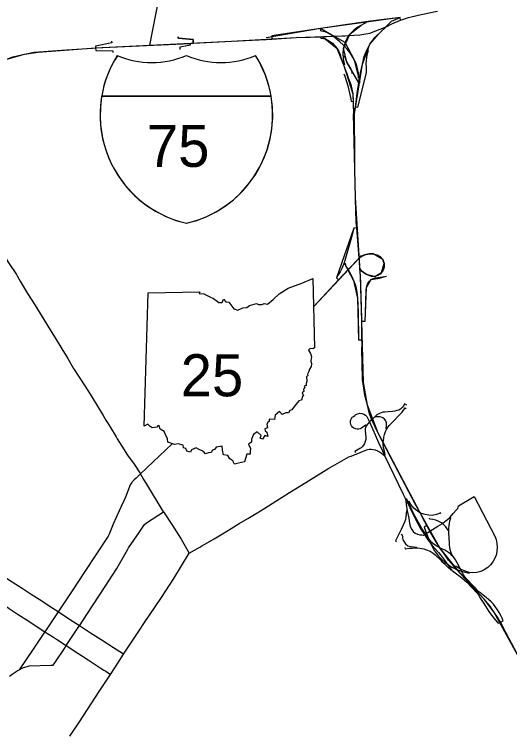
# Model space of a CAD drawing. Extents: x 0 to 750, y 0 to 507.
# Drawn here: x 349.21 to 379.68, y 258.49 to 302.57 of the extents above; entities that cross this region are included whole.
import ezdxf

# ---------------------------------------------------------------- set-up
doc = ezdxf.new("R2010")
doc.units = 0
for name, color, linetype in [('GM_P_US_Alignment', 7, 'Continuous'), ('GM_X_Interchange_Ramps', 7, 'Continuous'), ('GM_X_Interstate_Route', 7, 'Continuous'), ('GM_X_State_Route', 7, 'Continuous'), ('SH_Data', 7, 'Continuous')]:
    doc.layers.add(name, color=color, linetype=linetype)

msp = doc.modelspace()

# ---------------------------------------------------------------- linework, layer by layer
at = {"layer": 'GM_P_US_Alignment'}
for points in [[(370.147, 296.454), (370.629, 299.509), (371.075, 300.734), (371.605, 301.353), (372.411, 302.16), (372.954, 302.377), (368.055, 301.698), (364.701, 301.126)], [(370.496, 298.378), (370.147, 299.745), (369.564, 300.837), (368.055, 301.698)], [(370.396, 298.362), (369.661, 299.63), (369.459, 300.495), (369.879, 301.375), (370.529, 301.893)], [(343.47, 298.742), (344.535, 298.603), (345.804, 298.696), (346.876, 299.049), (348.761, 299.812), (349.837, 300.119), (350.674, 300.247), (354.214, 300.508), (362.568, 300.914), (366.547, 301.142), (368.825, 301.223)], [(368.153, 301.202), (369.043, 300.485), (369.5, 299.366), (370.043, 297.689), (370.08, 296.454)], [(380.488, 262.562), (378.714, 265.798), (378.115, 266.581), (376.609, 268.21), (375.388, 269.749), (373.902, 272.374), (372.62, 274.824), (371.601, 276.797), (370.929, 278.518), (370.691, 279.91), (370.58, 283.693), (370.508, 286.44), (370.197, 291.277), (370.08, 296.454)], [(370.272, 289.427), (370.089, 289.418), (369.03, 286.363), (369.156, 286.237)], [(370.569, 286.788), (370.846, 286.582), (371.387, 286.445), (371.808, 286.684), (371.96, 287.235), (371.878, 287.478), (371.296, 287.838), (371.045, 287.829), (370.78, 287.761), (370.427, 287.575), (367.64, 284.59)], [(369.495, 287.27), (370.081, 286.185), (370.328, 285.104), (370.371, 284.24), (370.389, 282.532)], [(370.784, 283.685), (370.875, 285.764), (371.172, 286.245), (371.667, 286.344), (372.108, 286.462)]]:
    msp.add_lwpolyline(points, dxfattribs=at)
at = {"layer": 'GM_X_Interchange_Ramps'}
for points in [[(372.959, 302.218), (372.954, 302.377), (371.122, 302.15), (370.834, 302.109), (369.43, 301.908), (368.055, 301.698), (365.055, 301.239), (365.062, 301.051)], [(370.834, 302.109), (370.836, 302.04), (370.714, 301.981), (370.529, 301.893), (370.341, 301.774), (370.096, 301.592), (369.879, 301.375), (369.772, 301.268), (369.648, 301.033), (369.564, 300.837), (369.494, 300.634), (369.459, 300.495), (369.435, 300.365), (369.428, 300.224), (369.428, 300.059), (369.433, 299.99), (369.446, 299.793), (369.514, 299.489), (369.459, 299.467)], [(370.441, 298.661), (370.38, 298.668), (370.375, 298.954), (370.345, 299.137), (370.311, 299.319), (370.239, 299.52), (370.147, 299.745), (370.002, 299.999), (369.872, 300.192), (369.686, 300.423), (369.494, 300.634), (369.459, 300.673), (369.212, 300.907), (368.998, 301.093), (368.825, 301.223), (368.784, 301.254), (368.522, 301.414), (368.331, 301.49), (368.126, 301.541), (368.06, 301.552), (368.055, 301.698)], [(360.218, 300.793), (360.208, 301.029), (359.304, 301.104), (359.3, 301.104), (359.297, 301.179)], [(359.297, 301.179), (359.304, 301.104), (360.208, 301.029), (360.218, 300.793)], [(368.074, 301.196), (368.077, 301.11), (368.093, 301.108), (368.35, 301.058), (368.604, 300.924), (368.786, 300.791), (368.93, 300.639), (369.043, 300.485), (369.17, 300.286), (369.249, 300.094), (369.318, 299.863), (369.397, 299.62), (369.459, 299.467), (369.5, 299.366), (369.548, 299.211), (369.656, 298.92), (369.754, 298.656), (369.922, 298.251), (370.043, 297.689), (370.064, 297.227), (370.08, 296.454), (370.147, 296.454)], [(355.199, 300.926), (355.207, 300.813), (354.208, 300.604), (354.214, 300.508)], [(359.421, 300.411), (359.408, 300.566), (359.837, 300.66), (360.052, 300.695), (360.048, 300.785)], [(359.421, 300.411), (359.408, 300.566), (359.837, 300.66), (360.052, 300.695), (360.048, 300.785)], [(354.214, 300.508), (354.218, 300.35), (355.272, 300.318), (355.264, 300.231)], [(370.874, 298.989), (370.876, 299.085), (370.868, 299.293), (370.857, 299.534), (370.872, 299.723), (370.894, 299.896), (370.926, 300.071), (370.965, 300.227), (371.006, 300.364), (370.912, 300.405)], [(369.433, 299.99), (369.514, 300.004), (369.582, 299.802), (369.661, 299.63), (369.764, 299.438), (369.905, 299.194), (369.976, 299.023), (369.984, 298.937)], [(369.491, 298.913), (369.535, 298.761), (369.718, 298.18), (369.914, 297.372), (369.941, 297.217), (370.064, 297.227)], [(370.193, 296.874), (370.337, 296.858), (370.865, 298.885), (370.874, 298.989)], [(370.272, 289.427), (370.089, 289.418), (370.024, 289.08), (369.894, 288.633), (369.495, 287.27), (369.356, 286.922), (369.247, 286.718), (369.135, 286.541), (369.03, 286.363), (369.156, 286.237)], [(369.495, 287.27), (369.56, 287.235), (369.603, 287.061), (369.66, 286.966), (369.738, 286.875)], [(369.738, 286.875), (369.816, 286.753), (369.946, 286.484), (370.081, 286.185), (370.172, 285.942), (370.233, 285.716), (370.28, 285.473), (370.328, 285.104), (370.361, 283.488), (370.364, 283.341), (370.389, 282.532), (370.598, 282.532)], [(370.58, 283.693), (370.784, 283.685), (370.819, 284.175), (370.862, 285.59), (370.875, 285.764), (370.908, 285.906), (370.961, 286.022), (371.056, 286.152), (371.172, 286.245), (371.287, 286.305), (371.422, 286.358), (372.008, 286.445), (372.108, 286.462)], [(373.363, 278.529), (373.221, 278.6), (373.164, 278.498), (373.071, 278.381), (372.958, 278.281), (372.861, 278.222), (372.742, 278.184), (372.628, 278.151), (372.466, 278.129), (372.2, 278.114), (372.003, 278.097), (371.882, 278.079), (371.787, 278.05), (371.675, 277.999), (371.517, 277.915), (371.391, 277.81), (371.276, 277.704), (371.196, 277.623), (371.131, 277.565), (371.054, 277.485), (370.951, 277.376), (370.873, 277.265), (370.823, 277.157), (370.801, 277.055), (370.799, 276.942), (370.836, 276.551), (370.827, 276.415), (370.803, 276.291), (370.758, 276.163), (370.697, 276.052), (370.616, 275.961), (370.539, 275.903), (370.463, 275.855), (370.161, 275.675), (370.197, 275.598)], [(371.983, 275.432), (372.029, 275.458), (371.974, 275.697), (371.947, 275.812), (371.919, 275.951), (371.911, 276.048), (371.905, 276.216), (371.917, 276.351), (371.934, 276.491), (371.944, 276.555), (371.985, 276.717), (372.019, 276.831), (372.062, 276.936), (372.106, 277.029), (372.169, 277.134), (372.27, 277.27), (372.408, 277.418), (372.989, 278.001), (373.073, 278.087), (373.262, 278.347), (373.314, 278.324)], [(370.873, 277.265), (370.812, 277.298), (370.559, 277.106), (370.488, 277.067), (370.396, 277.037), (370.296, 277.04), (370.194, 277.061), (370.102, 277.1), (370.02, 277.157), (369.948, 277.244), (369.907, 277.328), (369.89, 277.443), (369.894, 277.547), (369.916, 277.621), (369.952, 277.708), (370.003, 277.775), (370.067, 277.83), (370.15, 277.894), (370.23, 277.94), (370.336, 277.991), (370.444, 278.018), (370.598, 278.014), (370.713, 277.968), (370.814, 277.901), (370.892, 277.816), (370.941, 277.736), (371.054, 277.485), (371.623, 276.222), (371.855, 275.713), (371.958, 275.484), (371.983, 275.432)], [(372.106, 277.029), (372.076, 277.072), (372.101, 277.29), (372.101, 277.424), (372.061, 277.552), (371.981, 277.664), (371.875, 277.741), (371.773, 277.777), (371.693, 277.799), (371.602, 277.806), (371.493, 277.799), (371.413, 277.781), (371.391, 277.81)], [(376.169, 269.269), (376.151, 269.253), (376.064, 269.342), (375.93, 269.447), (375.807, 269.531), (375.695, 269.588), (375.518, 269.676), (375.388, 269.749), (375.356, 269.765), (375.195, 269.845), (375.04, 269.945), (374.901, 270.066), (374.762, 270.216), (374.674, 270.347), (374.506, 270.595), (374.277, 270.926), (373.977, 271.482), (373.77, 271.859), (373.433, 272.565), (373.333, 272.765), (373.267, 272.727)], [(373.3, 272.584), (373.367, 272.608), (373.717, 271.834), (373.917, 271.459), (374.216, 270.894), (374.439, 270.553), (374.651, 270.227), (374.803, 270.032), (374.915, 269.89), (375.302, 269.458), (375.418, 269.312), (375.62, 269.066), (375.807, 268.802), (375.84, 268.747), (376.003, 268.511), (376.111, 268.388), (376.135, 268.361), (376.253, 268.256), (376.417, 268.138), (376.645, 267.969), (376.89, 267.764), (377.038, 267.628), (377.69, 266.95), (377.78, 266.819), (377.87, 266.65), (378.047, 266.38), (378.188, 266.148), (378.402, 265.825), (378.62, 265.52), (378.916, 265.156), (378.98, 265.097), (379.114, 265.163)], [(375.451, 271.834), (375.423, 271.888), (375.303, 271.836), (375.181, 271.793), (374.916, 271.736), (374.709, 271.752), (374.478, 271.784), (374.258, 271.852), (374.171, 271.901), (374.007, 271.991), (373.789, 272.183), (373.613, 272.399), (373.494, 272.596), (373.433, 272.565)], [(373.379, 272.012), (373.33, 272.009), (373.321, 271.832), (373.3, 271.657), (373.266, 271.486), (373.222, 271.33), (373.13, 271.134), (373.002, 270.877), (372.786, 270.417), (372.662, 270.164), (372.714, 270.124)], [(375.937, 270.792), (375.891, 270.787), (375.843, 270.917), (375.762, 271.042), (375.682, 271.122), (375.546, 271.242), (375.489, 271.275), (375.291, 271.385), (375.144, 271.438), (374.949, 271.482), (374.767, 271.495), (374.761, 271.557)], [(379.114, 265.163), (379.292, 265.245), (379.224, 265.413), (379.142, 265.584), (379.035, 265.77), (378.941, 265.922), (378.8, 266.123), (378.682, 266.267), (378.541, 266.417), (378.381, 266.56), (378.227, 266.685), (378.051, 266.827), (377.901, 266.949), (377.79, 267.041), (377.487, 267.351), (376.991, 267.878), (376.877, 268.027), (376.779, 268.19), (376.723, 268.299), (376.652, 268.433), (376.433, 268.855), (376.349, 269.003), (376.26, 269.123), (376.169, 269.269), (376.091, 269.442), (376.032, 269.631), (376.005, 269.754), (375.982, 269.922), (375.955, 270.43), (375.941, 270.587), (375.937, 270.792), (375.932, 270.897), (375.953, 271.131), (375.975, 271.247), (376.007, 271.411), (376.064, 271.579), (376.025, 271.627)], [(374.591, 271.107), (374.414, 271.01), (374.562, 270.631), (374.674, 270.347), (374.803, 270.032), (374.97, 269.705), (375.064, 269.552), (375.178, 269.388), (375.309, 269.225), (375.509, 269.021), (375.724, 268.835), (375.84, 268.747), (376.124, 268.558), (376.393, 268.424), (376.413, 268.415), (376.723, 268.299), (376.953, 268.239), (377.186, 268.179), (377.188, 268.23)], [(373.006, 270.582), (373.08, 270.546), (373.087, 270.394), (373.121, 270.234), (373.191, 270.1), (373.282, 269.985), (373.414, 269.873), (373.613, 269.825), (373.951, 269.776), (373.954, 269.743)], [(373.23, 269.754), (373.255, 269.683), (373.512, 269.716), (373.694, 269.725), (373.837, 269.739), (373.954, 269.743), (374.15, 269.722), (374.4, 269.681), (374.57, 269.627), (374.788, 269.534), (374.984, 269.408), (375.102, 269.316), (375.418, 268.999), (375.515, 268.904), (375.625, 268.798), (375.887, 268.55), (376.089, 268.363), (376.111, 268.388)]]:
    msp.add_lwpolyline(points, dxfattribs=at)
at = {"layer": 'GM_X_Interstate_Route'}
for p, q in [((354.585, 297.533), (365.009, 297.533)), ((365.009, 297.533), (354.585, 297.533)), ((365.009, 297.533), (354.585, 297.533)), ((357.208, 277.235), (357.438, 285.442)), ((357.208, 277.235), (357.438, 285.442))]:
    msp.add_line(p, q, dxfattribs=at)
for points in [[(372.088, 301.799), (372.436, 301.978), (372.959, 302.218), (373.469, 302.386), (374.053, 302.513), (375.127, 302.741), (375.239, 302.766)], [(369.526, 301.252), (369.536, 301.253), (369.772, 301.268), (370.473, 301.313), (371.073, 301.418), (372.088, 301.799)], [(370.912, 300.405), (371.075, 300.734), (371.386, 301.138), (372.088, 301.799)], [(348.321, 299.62), (348.483, 299.69), (348.761, 299.812), (349.118, 299.953), (349.47, 300.048), (349.837, 300.119), (350.425, 300.236), (352.431, 300.391), (354.021, 300.496), (354.214, 300.508), (357.336, 300.661), (360.048, 300.785), (360.218, 300.793), (362.568, 300.914), (364.7, 301.031), (365.062, 301.051), (366.547, 301.142), (367.419, 301.173)], [(367.419, 301.173), (368.074, 301.196), (368.825, 301.223), (369.391, 301.244), (369.526, 301.252)], [(370.42, 298.524), (370.441, 298.661), (370.517, 298.965), (370.629, 299.509), (370.742, 299.977), (370.819, 300.183), (370.912, 300.405)], [(370.272, 289.427), (370.242, 289.763), (370.235, 289.864), (370.221, 290.428), (370.197, 291.277), (370.16, 293.027), (370.15, 294.512), (370.134, 295.707), (370.147, 296.454), (370.193, 296.874), (370.321, 297.87), (370.396, 298.362), (370.42, 298.524)], [(370.444, 287.34), (370.427, 287.575), (370.272, 289.427)], [(370.472, 286.948), (370.444, 287.34)], [(370.532, 286), (370.508, 286.44), (370.472, 286.948)], [(357.438, 285.442), (360.623, 285.496), (360.573, 285.397), (360.873, 285.376), (361.192, 285.2), (361.462, 285.09), (361.793, 284.829), (361.99, 284.832), (362.074, 285.046), (362.225, 284.881), (362.405, 284.851), (362.715, 284.458), (362.971, 284.373), (363.278, 284.508), (363.508, 284.53), (363.675, 284.663), (364.112, 284.777), (364.234, 284.709), (364.465, 284.722), (364.582, 284.773), (364.784, 284.728), (365.139, 285.026), (365.504, 285.378), (366.067, 285.71), (366.907, 286.025), (367.571, 286.306), (367.667, 282.047)], [(357.438, 285.442), (360.623, 285.496), (360.573, 285.397), (360.873, 285.376), (361.192, 285.2), (361.462, 285.09), (361.793, 284.829), (361.99, 284.832), (362.074, 285.046), (362.225, 284.881), (362.405, 284.851), (362.715, 284.458), (362.971, 284.373), (363.278, 284.508), (363.508, 284.53), (363.675, 284.663), (364.112, 284.777), (364.234, 284.709), (364.465, 284.722), (364.582, 284.773), (364.784, 284.728), (365.139, 285.026), (365.504, 285.378), (366.067, 285.71), (366.907, 286.025), (367.571, 286.306), (367.667, 282.047)], [(374.724, 270.857), (374.591, 271.107), (374.348, 271.566), (374.171, 271.901), (373.554, 273.069), (371.905, 276.216), (371.819, 276.381), (371.601, 276.797), (371.196, 277.623), (371.061, 277.995), (370.929, 278.518), (370.77, 279.145), (370.706, 279.564), (370.638, 280.107), (370.615, 281.12), (370.61, 281.202), (370.598, 281.85), (370.607, 282.35), (370.598, 282.532), (370.593, 283.116), (370.58, 283.693), (370.579, 283.846), (370.559, 284.554), (370.541, 285.22), (370.537, 285.911), (370.532, 286)], [(367.667, 282.047), (367.569, 281.987), (367.416, 282.015), (367.314, 281.896), (367.441, 281.696), (367.501, 281.486), (367.448, 281.254), (367.5, 281.062), (367.464, 280.902), (367.368, 280.743), (367.335, 280.591), (367.254, 280.43), (367.261, 280.341), (367.183, 280.27), (367.197, 280.003), (367.158, 279.856), (367.171, 279.729), (367.045, 279.695), (367.074, 279.59), (366.994, 279.509), (367.011, 279.369), (366.92, 279.28), (367.008, 279.101), (366.937, 279.044), (366.879, 278.827), (366.717, 278.783), (366.393, 278.385), (366.279, 278.235), (366.15, 278.198), (366.08, 278.043), (365.922, 278.043), (365.682, 277.936), (365.528, 278.12), (365.257, 277.898), (365.225, 277.642), (364.883, 277.651), (364.896, 277.521), (364.82, 277.484), (364.75, 277.354), (364.791, 277.124), (364.63, 277.065), (364.65, 276.931), (364.752, 276.849), (364.798, 276.594), (364.628, 276.646), (364.488, 276.43), (364.344, 276.481), (364.391, 276.663), (364.149, 276.883), (363.919, 276.707), (363.8, 276.426), (363.798, 276.237), (363.627, 276.123), (363.737, 275.856), (363.717, 275.672), (363.72, 275.498), (363.506, 275.504), (363.377, 275.033)], [(367.667, 282.047), (367.569, 281.987), (367.416, 282.015), (367.314, 281.896), (367.441, 281.696), (367.501, 281.486), (367.448, 281.254), (367.5, 281.062), (367.464, 280.902), (367.368, 280.743), (367.335, 280.591), (367.254, 280.43), (367.261, 280.341), (367.183, 280.27), (367.197, 280.003), (367.158, 279.856), (367.171, 279.729), (367.045, 279.695), (367.074, 279.59), (366.994, 279.509), (367.011, 279.369), (366.92, 279.28), (367.008, 279.101), (366.937, 279.044), (366.879, 278.827), (366.717, 278.783), (366.393, 278.385), (366.279, 278.235), (366.15, 278.198), (366.08, 278.043), (365.922, 278.043), (365.682, 277.936), (365.528, 278.12), (365.257, 277.898), (365.225, 277.642), (364.883, 277.651), (364.896, 277.521), (364.82, 277.484), (364.75, 277.354), (364.791, 277.124), (364.63, 277.065), (364.65, 276.931), (364.752, 276.849), (364.798, 276.594), (364.628, 276.646), (364.488, 276.43), (364.344, 276.481), (364.391, 276.663), (364.149, 276.883), (363.919, 276.707), (363.8, 276.426), (363.798, 276.237), (363.627, 276.123), (363.737, 275.856), (363.717, 275.672), (363.72, 275.498), (363.506, 275.504), (363.377, 275.033)], [(363.377, 275.033), (363.005, 274.943), (362.747, 274.889), (362.656, 275.103), (362.472, 275.215), (362.352, 275.431), (362.087, 275.46), (362.024, 275.756), (361.995, 275.996), (361.633, 275.937), (361.533, 275.79), (361.405, 275.751), (361.33, 275.603), (361.155, 275.591), (360.967, 275.521), (360.844, 275.666), (360.536, 275.812), (360.398, 275.887), (360.108, 275.77), (360.047, 275.632), (359.816, 275.693), (359.762, 275.847), (359.623, 275.893), (359.592, 276.057), (359.294, 276.144), (359.066, 276.109), (358.664, 276.241), (358.64, 276.456), (358.503, 276.718), (358.432, 276.9), (358.177, 277.039), (358.126, 277.255), (358.045, 277.249), (357.97, 277.161), (357.688, 277.121), (357.575, 277.209), (357.417, 277.36), (357.208, 277.235)], [(363.377, 275.033), (363.005, 274.943), (362.747, 274.889), (362.656, 275.103), (362.472, 275.215), (362.352, 275.431), (362.087, 275.46), (362.024, 275.756), (361.995, 275.996), (361.633, 275.937), (361.533, 275.79), (361.405, 275.751), (361.33, 275.603), (361.155, 275.591), (360.967, 275.521), (360.844, 275.666), (360.536, 275.812), (360.398, 275.887), (360.108, 275.77), (360.047, 275.632), (359.816, 275.693), (359.762, 275.847), (359.623, 275.893), (359.592, 276.057), (359.294, 276.144), (359.066, 276.109), (358.664, 276.241), (358.64, 276.456), (358.503, 276.718), (358.432, 276.9), (358.177, 277.039), (358.126, 277.255), (358.045, 277.249), (357.97, 277.161), (357.688, 277.121), (357.575, 277.209), (357.417, 277.36), (357.208, 277.235)], [(376.225, 268.627), (375.93, 268.99), (375.664, 269.343), (375.388, 269.749), (375.096, 270.206), (374.775, 270.759), (374.724, 270.857)], [(378.541, 266.047), (378.456, 266.17), (378.115, 266.581), (377.773, 266.958), (376.413, 268.415), (376.283, 268.555), (376.225, 268.627)], [(379.292, 264.838), (379.279, 264.862), (379.114, 265.163), (378.944, 265.47), (378.714, 265.798), (378.541, 266.047)], [(382.857, 257.191), (382.546, 257.645), (382.309, 258.124), (382.037, 258.845), (381.875, 259.365), (381.727, 259.787), (381.611, 260.139), (381.491, 260.445), (381.31, 260.871), (381.114, 261.332), (381.088, 261.394), (380.661, 262.212), (380.488, 262.562), (379.292, 264.838)]]:
    msp.add_lwpolyline(points, dxfattribs=at)
for centre, radius, start, end in [((361.339, 296.385), 6.851, 147.8216, 256.9941), ((360.911, 296.504), 6.409, 146.654, 170.759), ((357.669, 305.069), 5.467, 247.0848, 292.9105), ((357.669, 305.069), 5.467, 247.0848, 292.9105), ((358.255, 296.385), 6.851, 283.0065, 32.1787), ((361.925, 305.07), 5.468, 247.0916, 292.9084), ((361.925, 305.07), 5.468, 247.0916, 292.9084), ((358.255, 296.385), 6.851, 9.6475, 32.179), ((361.339, 296.385), 6.851, 170.3514, 256.9967), ((358.269, 296.382), 6.838, 282.7667, 9.6898)]:
    msp.add_arc(centre, radius, start, end, dxfattribs=at)
at = {"layer": 'GM_X_State_Route'}
for points in [[(346.637, 290.936), (347.566, 289.411), (347.989, 288.765), (348.221, 288.351), (348.403, 288.042), (348.838, 287.316), (349.336, 286.555), (349.383, 286.471), (349.564, 286.141), (350.015, 285.386), (350.468, 284.692), (350.639, 284.42), (351.424, 283.165), (351.784, 282.568), (352.133, 281.988), (352.511, 281.391), (352.86, 280.786), (353.205, 280.235), (353.588, 279.638), (353.974, 279.041), (354.319, 278.461), (354.668, 277.885), (354.832, 277.599), (354.914, 277.472)], [(368.635, 285.671), (369.156, 286.237), (369.738, 286.875), (370.427, 287.575), (370.556, 287.706)], [(368.635, 285.671), (369.156, 286.237), (369.738, 286.875), (370.427, 287.575), (370.556, 287.706)], [(368.635, 285.671), (369.156, 286.237), (369.738, 286.875), (370.427, 287.575), (370.556, 287.706)], [(370.556, 287.706), (370.78, 287.761), (371.045, 287.829), (371.296, 287.838), (371.53, 287.777), (371.717, 287.669), (371.878, 287.478), (371.96, 287.235), (371.96, 287.014), (371.895, 286.827), (371.808, 286.684), (371.708, 286.584), (371.578, 286.501), (371.387, 286.445), (371.179, 286.441), (371.023, 286.497), (370.846, 286.582), (370.691, 286.678), (370.569, 286.788), (370.472, 286.948)], [(367.64, 284.59), (368.635, 285.671)], [(367.64, 284.59), (368.635, 285.671)], [(367.64, 284.59), (368.635, 285.671)], [(354.914, 277.472), (355.131, 277.136), (355.475, 276.577), (355.534, 276.455), (355.828, 276.005), (356.182, 275.434), (356.586, 274.894), (356.964, 274.297)], [(356.964, 274.297), (358.914, 276.15)], [(369.783, 275.348), (369.926, 275.382), (370.478, 275.602), (370.882, 275.766), (371.036, 275.807), (371.166, 275.81), (371.29, 275.801), (371.417, 275.769), (371.559, 275.714), (371.669, 275.651), (371.793, 275.561), (371.891, 275.491), (371.983, 275.432)], [(368.555, 274.634), (368.779, 274.772), (369.783, 275.348)], [(371.983, 275.432), (373.123, 273.043), (373.224, 272.834)], [(356.964, 274.297), (356.7, 274.037)], [(358.395, 271.965), (357.37, 273.652), (357.144, 274.014), (356.964, 274.297)], [(363.985, 271.798), (364.088, 271.861), (364.626, 272.181), (365.074, 272.466), (366.133, 273.154), (367.139, 273.765), (368.555, 274.634)], [(356.449, 273.765), (356.344, 273.608), (356.047, 272.864), (355.66, 272.023), (355.3, 271.187), (355.041, 270.586)], [(356.7, 274.037), (356.578, 273.916), (356.469, 273.795), (356.449, 273.765)], [(377.501, 272.898), (378.763, 270.464), (378.846, 270.243), (378.896, 270.017), (378.915, 269.782), (378.892, 269.52), (378.846, 269.28), (378.758, 269.059), (378.657, 268.87), (378.51, 268.686), (378.335, 268.529), (378.118, 268.382), (377.902, 268.29), (377.671, 268.23), (377.418, 268.198), (377.188, 268.23), (376.957, 268.299), (376.741, 268.383), (376.652, 268.433), (376.553, 268.491), (376.384, 268.585), (376.225, 268.627)], [(376.545, 272.327), (377.501, 272.898)], [(373.224, 272.834), (373.233, 272.813), (373.267, 272.727), (373.293, 272.631), (373.3, 272.584), (373.323, 272.424), (373.379, 272.012), (373.475, 271.567), (373.505, 271.383), (373.531, 271.265), (373.549, 271.155), (373.585, 271.002), (373.659, 270.863), (373.738, 270.75), (373.864, 270.65), (374.003, 270.581), (374.151, 270.546), (374.277, 270.533), (374.392, 270.524)], [(374.392, 270.524), (374.439, 270.553), (374.483, 270.58), (374.506, 270.595), (374.562, 270.631), (374.611, 270.662), (374.775, 270.759), (375.269, 271.065), (375.407, 271.146), (375.546, 271.242), (375.702, 271.353), (375.863, 271.477), (376.025, 271.627), (376.21, 271.852), (376.405, 272.073), (376.491, 272.169), (376.545, 272.327)], [(356.171, 269.609), (356.242, 269.737), (356.887, 270.692), (357.211, 271.181), (357.338, 271.271), (358.395, 271.965)], [(358.395, 271.965), (358.944, 271.119), (359.327, 270.503)], [(360.746, 269.854), (360.964, 269.992), (361.513, 270.295), (362.022, 270.61), (362.545, 270.921), (363.045, 271.235), (363.577, 271.548), (363.985, 271.798)], [(355.041, 270.586), (354.983, 270.451), (354.23, 269.305)], [(359.327, 270.503), (359.468, 270.276), (359.974, 269.403)], [(359.974, 269.403), (360.621, 269.775), (360.746, 269.854)], [(353.984, 266.116), (354.061, 266.233), (354.808, 267.368), (355.528, 268.462), (356.171, 269.609)], [(357.311, 265.267), (357.534, 265.601), (358.258, 266.689), (359.031, 267.85), (359.974, 269.403)], [(354.23, 269.305), (353.509, 268.215)], [(351.907, 265.792), (351.427, 266.105), (350.9, 266.449), (350.255, 266.869), (349.696, 267.232), (349.078, 267.634), (348.553, 267.979), (347.946, 268.374), (347.47, 268.813)], [(353.509, 268.215), (352.765, 267.09), (352.694, 266.981)], [(346.488, 267.693), (347.135, 267.161), (348.182, 266.479), (348.275, 266.418), (348.3, 266.402), (348.903, 266.009), (349.458, 265.647), (350.161, 265.189), (350.626, 264.886), (351.096, 264.579)], [(352.694, 266.981), (351.907, 265.792)], [(353.14, 264.834), (353.213, 264.946), (353.984, 266.116)], [(351.907, 265.792), (351.096, 264.579)], [(353.213, 264.946), (353.213, 264.946), (352.612, 265.335), (351.907, 265.792)], [(355.926, 263.188), (355.314, 263.584), (354.551, 264.079), (353.904, 264.499), (353.213, 264.946)], [(355.926, 263.188), (356.791, 264.486), (357.311, 265.267)], [(351.096, 264.579), (351.035, 264.489), (350.372, 263.506), (349.519, 262.241)], [(351.096, 264.579), (351.621, 264.236)], [(352.333, 263.612), (352.408, 263.721), (353.14, 264.834)], [(351.621, 264.236), (351.621, 264.236), (351.812, 264.111), (352.408, 263.721)], [(352.408, 263.721), (352.408, 263.721), (353.128, 263.252), (353.75, 262.848), (354.503, 262.358), (354.722, 262.215), (354.832, 262.144), (355.13, 261.95)], [(351.592, 262.519), (351.592, 262.519), (351.695, 262.671), (352.333, 263.612)], [(355.13, 261.95), (355.13, 261.95), (355.575, 262.641), (355.926, 263.188)], [(348.907, 261.838), (348.914, 261.844), (349.081, 261.96), (349.384, 262.169), (349.519, 262.241), (349.727, 262.351), (350.124, 262.486), (351.459, 262.516)], [(351.459, 262.516), (351.466, 262.516), (351.592, 262.519)], [(352.623, 258.141), (352.708, 258.27), (353.212, 259.037), (354.435, 260.894), (355.13, 261.95)]]:
    msp.add_lwpolyline(points, dxfattribs=at)
at = {"layer": 'SH_Data'}
msp.add_line((365.785, 343.117), (357.52, 300.669), dxfattribs=at)

# ---------------------------------------------------------------- texts
at = {"layer": 'GM_X_Interstate_Route'}
for s, p in [('75', (357.366, 293.182)), ('25', (359.446, 279.065))]:
    msp.add_text(s, height=2.5875, dxfattribs=at).set_placement(p)

doc.saveas('drawing.dxf')
